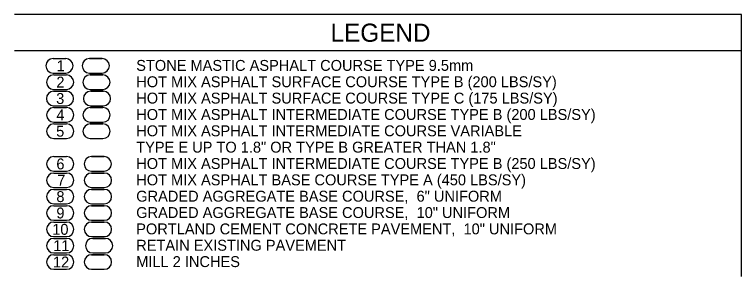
# Model space of a CAD drawing. Extents: x 2003207 to 2014043, y 843846 to 860154.
# Drawn here: x 2013615.72 to 2013655.72, y 844565.99 to 844580.41 of the extents above; entities that cross this region are included whole.
import ezdxf

# ---------------------------------------------------------------- set-up
doc = ezdxf.new("R2010")
doc.units = 0
for name, color, linetype in [('RD_EX_Road', 7, 'Continuous'), ('RD_EX_Road_txCode', 7, 'Continuous'), ('RD_QTY_ConcPave', 7, 'Continuous'), ('RD_QTY_Intermediate', 7, 'Continuous'), ('RD_QTY_Milling', 7, 'Continuous'), ('RD_QTY_Surf_Course', 7, 'Continuous'), ('RD_SHT_Bndy', 7, 'Continuous'), ('RD_TX_Misc2', 7, 'Continuous')]:
    doc.layers.add(name, color=color, linetype=linetype)

msp = doc.modelspace()

# ---------------------------------------------------------------- linework, layer by layer
at = {"layer": 'RD_EX_Road'}
for p, q in [((2013620.723, 844568.087), (2013620.023, 844568.087)), ((2013620.023, 844567.287), (2013620.723, 844567.287)), ((2013620.661, 844567.187), (2013619.961, 844567.187)), ((2013619.961, 844566.387), (2013620.661, 844566.387))]:
    msp.add_line(p, q, dxfattribs=at)
for centre, start, end in [((2013620.023, 844567.687), 90, 270), ((2013620.723, 844567.687), 270, 90), ((2013619.961, 844566.787), 90, 270), ((2013620.661, 844566.787), 270, 90)]:
    msp.add_arc(centre, 0.4, start, end, dxfattribs=at)
at = {"layer": 'RD_QTY_ConcPave'}
for p, q in [((2013620.661, 844570.787), (2013619.961, 844570.787)), ((2013619.961, 844569.987), (2013620.661, 844569.987)), ((2013620.661, 844569.887), (2013619.961, 844569.887)), ((2013619.961, 844569.087), (2013620.661, 844569.087)), ((2013620.661, 844568.987), (2013619.961, 844568.987)), ((2013619.961, 844568.187), (2013620.661, 844568.187))]:
    msp.add_line(p, q, dxfattribs=at)
for centre, start, end in [((2013619.961, 844570.387), 90, 270), ((2013620.661, 844570.387), 270, 90), ((2013619.961, 844569.487), 90, 270), ((2013620.661, 844569.487), 270, 90), ((2013619.961, 844568.587), 90, 270), ((2013620.661, 844568.587), 270, 90)]:
    msp.add_arc(centre, 0.4, start, end, dxfattribs=at)
at = {"layer": 'RD_QTY_Intermediate'}
for p, q in [((2013620.582, 844575.287), (2013619.882, 844575.287)), ((2013619.882, 844574.487), (2013620.582, 844574.487)), ((2013620.582, 844574.387), (2013619.882, 844574.387)), ((2013619.882, 844573.587), (2013620.582, 844573.587)), ((2013620.65, 844572.587), (2013619.95, 844572.587)), ((2013619.95, 844571.787), (2013620.65, 844571.787)), ((2013620.661, 844571.687), (2013619.961, 844571.687)), ((2013619.961, 844570.887), (2013620.661, 844570.887))]:
    msp.add_line(p, q, dxfattribs=at)
for centre, start, end in [((2013619.882, 844574.887), 90, 270), ((2013620.582, 844574.887), 270, 90), ((2013619.882, 844573.987), 90, 270), ((2013620.582, 844573.987), 270, 90), ((2013619.95, 844572.187), 90, 270), ((2013620.65, 844572.187), 270, 90), ((2013619.961, 844571.287), 90, 270), ((2013620.661, 844571.287), 270, 90)]:
    msp.add_arc(centre, 0.4, start, end, dxfattribs=at)
at = {"layer": 'RD_QTY_Milling'}
for p, q in [((2013620.661, 844567.187), (2013619.961, 844567.187)), ((2013619.961, 844566.387), (2013620.661, 844566.387))]:
    msp.add_line(p, q, dxfattribs=at)
for centre, start, end in [((2013619.961, 844566.787), 90, 270), ((2013620.661, 844566.787), 270, 90)]:
    msp.add_arc(centre, 0.4, start, end, dxfattribs=at)
at = {"layer": 'RD_QTY_Surf_Course'}
for p, q in [((2013620.542, 844577.987), (2013619.842, 844577.987)), ((2013619.842, 844577.187), (2013620.542, 844577.187)), ((2013620.576, 844577.087), (2013619.876, 844577.087)), ((2013619.876, 844576.287), (2013620.576, 844576.287)), ((2013620.61, 844576.187), (2013619.91, 844576.187)), ((2013619.91, 844575.387), (2013620.61, 844575.387))]:
    msp.add_line(p, q, dxfattribs=at)
for centre, start, end in [((2013619.842, 844577.587), 90, 270), ((2013620.542, 844577.587), 270, 90), ((2013619.876, 844576.687), 90, 270), ((2013620.576, 844576.687), 270, 90), ((2013619.91, 844575.787), 90, 270), ((2013620.61, 844575.787), 270, 90)]:
    msp.add_arc(centre, 0.4, start, end, dxfattribs=at)
at = {"layer": 'RD_SHT_Bndy'}
for p, q in [((2013655.721, 844580.41), (2013615.721, 844580.41)), ((2013655.721, 844578.41), (2013655.721, 844580.41)), ((2013655.721, 844578.41), (2013615.721, 844578.41)), ((2013655.721, 844565.992), (2013655.721, 844578.41))]:
    msp.add_line(p, q, dxfattribs=at)
at = {"layer": 'RD_TX_Misc2'}
for p, q in [((2013617.842, 844577.987), (2013618.542, 844577.987)), ((2013619.842, 844577.987), (2013620.542, 844577.987)), ((2013617.842, 844577.187), (2013618.542, 844577.187)), ((2013617.876, 844577.087), (2013618.576, 844577.087)), ((2013619.842, 844577.187), (2013620.542, 844577.187)), ((2013619.876, 844577.087), (2013620.576, 844577.087)), ((2013617.871, 844576.187), (2013618.571, 844576.187)), ((2013617.876, 844576.287), (2013618.576, 844576.287)), ((2013619.876, 844576.287), (2013620.576, 844576.287)), ((2013619.91, 844576.187), (2013620.61, 844576.187)), ((2013617.871, 844575.387), (2013618.571, 844575.387)), ((2013617.882, 844575.287), (2013618.582, 844575.287)), ((2013619.882, 844575.287), (2013620.582, 844575.287)), ((2013619.91, 844575.387), (2013620.61, 844575.387)), ((2013617.882, 844574.487), (2013618.582, 844574.487)), ((2013619.882, 844574.487), (2013620.582, 844574.487)), ((2013617.882, 844574.387), (2013618.582, 844574.387)), ((2013619.882, 844574.387), (2013620.582, 844574.387)), ((2013617.882, 844573.587), (2013618.582, 844573.587)), ((2013619.882, 844573.587), (2013620.582, 844573.587)), ((2013617.882, 844572.587), (2013618.582, 844572.587)), ((2013619.95, 844572.587), (2013620.65, 844572.587)), ((2013617.882, 844571.787), (2013618.582, 844571.787)), ((2013617.882, 844571.687), (2013618.582, 844571.687)), ((2013619.95, 844571.787), (2013620.65, 844571.787)), ((2013619.961, 844571.687), (2013620.661, 844571.687)), ((2013617.882, 844570.887), (2013618.582, 844570.887)), ((2013619.961, 844570.887), (2013620.661, 844570.887)), ((2013617.882, 844570.787), (2013618.582, 844570.787)), ((2013619.961, 844570.787), (2013620.661, 844570.787)), ((2013617.882, 844569.987), (2013618.582, 844569.987)), ((2013617.882, 844569.887), (2013618.582, 844569.887)), ((2013619.961, 844569.987), (2013620.661, 844569.987)), ((2013619.961, 844569.887), (2013620.661, 844569.887)), ((2013617.882, 844569.087), (2013618.582, 844569.087)), ((2013617.882, 844568.987), (2013618.582, 844568.987)), ((2013619.961, 844569.087), (2013620.661, 844569.087)), ((2013619.961, 844568.987), (2013620.661, 844568.987)), ((2013617.882, 844568.187), (2013618.582, 844568.187)), ((2013617.882, 844568.087), (2013618.582, 844568.087)), ((2013619.961, 844568.187), (2013620.661, 844568.187)), ((2013620.023, 844568.087), (2013620.723, 844568.087)), ((2013617.882, 844567.287), (2013618.582, 844567.287)), ((2013620.023, 844567.287), (2013620.723, 844567.287)), ((2013617.882, 844567.187), (2013618.582, 844567.187)), ((2013619.961, 844567.187), (2013620.661, 844567.187)), ((2013617.882, 844566.387), (2013618.582, 844566.387)), ((2013619.961, 844566.387), (2013620.661, 844566.387))]:
    msp.add_line(p, q, dxfattribs=at)
for centre, start, end in [((2013617.842, 844577.587), 90, 270), ((2013618.542, 844577.587), 270, 90), ((2013619.842, 844577.587), 90, 270), ((2013620.542, 844577.587), 270, 90), ((2013617.876, 844576.687), 90, 270), ((2013618.576, 844576.687), 270, 90), ((2013619.876, 844576.687), 90, 270), ((2013620.576, 844576.687), 270, 90), ((2013617.871, 844575.787), 90, 270), ((2013618.571, 844575.787), 270, 90), ((2013619.91, 844575.787), 90, 270), ((2013620.61, 844575.787), 270, 90), ((2013617.882, 844574.887), 90, 270), ((2013618.582, 844574.887), 270, 90), ((2013619.882, 844574.887), 90, 270), ((2013620.582, 844574.887), 270, 90), ((2013617.882, 844573.987), 90, 270), ((2013618.582, 844573.987), 270, 90), ((2013619.882, 844573.987), 90, 270), ((2013620.582, 844573.987), 270, 90), ((2013617.882, 844572.187), 90, 270), ((2013618.582, 844572.187), 270, 90), ((2013619.95, 844572.187), 90, 270), ((2013620.65, 844572.187), 270, 90), ((2013617.882, 844571.287), 90, 270), ((2013618.582, 844571.287), 270, 90), ((2013619.961, 844571.287), 90, 270), ((2013620.661, 844571.287), 270, 90), ((2013617.882, 844570.387), 90, 270), ((2013618.582, 844570.387), 270, 90), ((2013619.961, 844570.387), 90, 270), ((2013620.661, 844570.387), 270, 90), ((2013617.882, 844569.487), 90, 270), ((2013618.582, 844569.487), 270, 90), ((2013619.961, 844569.487), 90, 270), ((2013620.661, 844569.487), 270, 90), ((2013617.882, 844568.587), 90, 270), ((2013618.582, 844568.587), 270, 90), ((2013619.961, 844568.587), 90, 270), ((2013620.661, 844568.587), 270, 90), ((2013617.882, 844567.687), 90, 270), ((2013618.582, 844567.687), 270, 90), ((2013620.023, 844567.687), 90, 270), ((2013620.723, 844567.687), 270, 90), ((2013617.882, 844566.787), 90, 270), ((2013618.582, 844566.787), 270, 90), ((2013619.961, 844566.787), 90, 270), ((2013620.661, 844566.787), 270, 90)]:
    msp.add_arc(centre, 0.4, start, end, dxfattribs=at)

# ---------------------------------------------------------------- texts
at = {"layer": 'RD_EX_Road_txCode'}
for s, height, p in [('LEGEND', 1, (2013633.11, 844578.91)), ('STONE MASTIC ASPHALT COURSE TYPE 9.5mm', 0.6, (2013622.417, 844577.31)), ('HOT MIX ASPHALT SURFACE COURSE TYPE B (200 LBS/SY)', 0.6, (2013622.417, 844576.41)), ('HOT MIX ASPHALT SURFACE COURSE TYPE C (175 LBS/SY)', 0.6, (2013622.417, 844575.51)), ('HOT MIX ASPHALT INTERMEDIATE COURSE TYPE B (200 LBS/SY)', 0.6, (2013622.417, 844574.61)), ('HOT MIX ASPHALT INTERMEDIATE COURSE VARIABLE ', 0.6, (2013622.417, 844573.71)), ('TYPE E UP TO 1.8" OR TYPE B GREATER THAN 1.8"', 0.6, (2013622.417, 844572.81)), ('HOT MIX ASPHALT INTERMEDIATE COURSE TYPE B (250 LBS/SY)', 0.6, (2013622.417, 844571.91)), ('HOT MIX ASPHALT BASE COURSE TYPE A (450 LBS/SY)', 0.6, (2013622.417, 844571.01)), ('GRADED AGGREGATE BASE COURSE,  6" UNIFORM', 0.6, (2013622.417, 844570.11)), ('GRADED AGGREGATE BASE COURSE,  10" UNIFORM', 0.6, (2013622.417, 844569.21)), ('PORTLAND CEMENT CONCRETE PAVEMENT,  10" UNIFORM', 0.6, (2013622.417, 844568.31)), ('RETAIN EXISTING PAVEMENT', 0.6, (2013622.417, 844567.41)), ('MILL 2 INCHES', 0.6, (2013622.417, 844566.51))]:
    msp.add_text(s, height=height, dxfattribs=at).set_placement(p)
at = {"layer": 'RD_TX_Misc2'}
for s, p in [('1', (2013618.039, 844577.287)), ('2', (2013618.022, 844576.387)), ('3', (2013618.011, 844575.487)), ('4', (2013618.023, 844574.587)), ('5', (2013618.011, 844573.687)), ('6', (2013618.023, 844571.887)), ('7 ', (2013618.066, 844570.987)), ('8', (2013618.023, 844570.087)), ('9', (2013618.023, 844569.187)), ('10', (2013617.796, 844568.287)), ('11', (2013617.852, 844567.387)), ('12', (2013617.835, 844566.487))]:
    msp.add_text(s, height=0.6, dxfattribs=at).set_placement(p)

doc.saveas('drawing.dxf')
